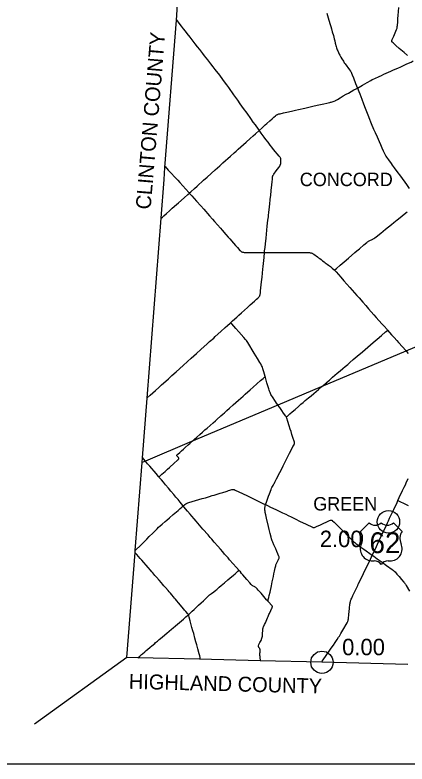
# Model space of a CAD drawing. Extents: x 1597222 to 1925846, y 496284 to 911751.
# Drawn here: x 1652634 to 1678855, y 496867 to 546977 of the extents above; entities that cross this region are included whole.
import ezdxf

# ---------------------------------------------------------------- set-up
doc = ezdxf.new("R2010")
doc.units = 0
for name, color, linetype in [('Default', 7, 'Continuous'), ('GM_X_Adjacent_County', 7, 'Continuous'), ('GM_X_Adjacent_County_Text', 7, 'Continuous'), ('GM_X_County', 7, 'Continuous'), ('GM_X_County_Road', 7, 'Continuous'), ('GM_X_Township', 7, 'Continuous'), ('GM_X_Township_Road', 7, 'Continuous'), ('GM_X_Township_Text', 7, 'Continuous'), ('GM_X_US_Route', 7, 'Continuous'), ('GM_X_US_Shield', 7, 'Continuous'), ('SC_Scratch1', 7, 'Continuous')]:
    doc.layers.add(name, color=color, linetype=linetype)

msp = doc.modelspace()

# ---------------------------------------------------------------- linework, layer by layer
at = {"layer": 'Default'}
for centre in [(1677611, 513068), (1677611, 513068), (1673168, 503670), (1673168, 503670)]:
    msp.add_circle(centre, 750, dxfattribs=at)
at = {"layer": 'GM_X_Adjacent_County'}
msp.add_line((1660124, 503996), (1653936, 499536), dxfattribs=at)
at = {"layer": 'GM_X_County'}
msp.add_lwpolyline([(1678903, 503534), (1673166, 503675), (1669035, 503777), (1664966, 503877), (1660848, 503978), (1660124, 503996), (1660668, 511007), (1660679, 511141), (1661136, 517041), (1661161, 517359), (1661469, 521334), (1662403, 533380), (1662603, 535965), (1662666, 536773), (1663431, 546640), (1663512, 547675)], dxfattribs=at)
at = {"layer": 'GM_X_County_Road'}
for points in [[(1673498, 547096), (1673586, 546780), (1673690, 546418), (1673753, 546197), (1673795, 546055), (1673856, 545851), (1673928, 545598), (1673982, 545392), (1674017, 545249), (1674056, 545089), (1674112, 544867), (1674139, 544772), (1674160, 544709), (1674184, 544648), (1674218, 544573), (1674318, 544366), (1674364, 544279), (1674435, 544150), (1674502, 544037), (1674597, 543883), (1674660, 543787), (1674717, 543707), (1675018, 543297), (1675065, 543229), (1675091, 543188), (1675114, 543145), (1675141, 543086), (1675184, 542979), (1675266, 542765), (1675314, 542643), (1675356, 542536), (1675416, 542383), (1675472, 542246), (1675533, 542090)], [(1675533, 542090), (1675880, 542286), (1676194, 542464), (1676435, 542603), (1676521, 542651), (1676594, 542688), (1676698, 542737), (1676982, 542865), (1677147, 542938), (1677312, 543011), (1677611, 543146), (1677776, 543218), (1677911, 543279), (1678060, 543347), (1678240, 543426), (1678435, 543514), (1678809, 543682), (1679063, 543796), (1679138, 543831), (1679196, 543862), (1679238, 543887), (1679273, 543912)], [(1668974, 539258), (1669157, 539423), (1669376, 539621), (1669486, 539719), (1669682, 539894), (1669828, 540026), (1669950, 540136), (1670061, 540233), (1670112, 540274), (1670152, 540301), (1670180, 540317), (1670210, 540330), (1670240, 540341), (1670287, 540355), (1670367, 540374), (1670591, 540423), (1670927, 540499), (1671215, 540566), (1671391, 540605), (1671599, 540653), (1672031, 540751), (1672559, 540869), (1672847, 540934), (1673295, 541035), (1673487, 541079), (1673583, 541101), (1673695, 541128), (1673743, 541140), (1673760, 541143), (1673776, 541147), (1673839, 541165), (1673917, 541191), (1673979, 541215), (1674039, 541242), (1674083, 541264), (1674197, 541330), (1674382, 541436), (1674595, 541558), (1674795, 541672), (1674938, 541753), (1675109, 541850), (1675308, 541963), (1675451, 542044), (1675533, 542090)], [(1675533, 542090), (1675623, 541865), (1675689, 541697), (1675824, 541345), (1675944, 541040), (1676063, 540734), (1676235, 540290), (1676347, 540000), (1676413, 539832), (1676505, 539603), (1676568, 539452), (1676620, 539331), (1676715, 539122), (1676850, 538823), (1676982, 538523), (1677075, 538313), (1677174, 538088), (1677262, 537893), (1677330, 537744), (1677366, 537670), (1677398, 537612), (1677440, 537542), (1677486, 537473), (1677618, 537286), (1677792, 537047), (1677869, 536940), (1678005, 536756), (1678247, 536425), (1678353, 536278), (1678527, 536040), (1678710, 535787), (1678825, 535628), (1679008, 535376)], [(1664301, 535065), (1664310, 535073), (1664395, 535150), (1664639, 535370), (1664810, 535522), (1665251, 535916), (1665482, 536125), (1665751, 536366), (1666031, 536618), (1666325, 536881), (1666544, 537078), (1667057, 537538), (1667288, 537747), (1667423, 537868), (1667569, 538000), (1667740, 538153), (1668095, 538470), (1668364, 538710), (1668572, 538896), (1668718, 539028), (1668974, 539258)], [(1662674, 536831), (1662885, 536604), (1663052, 536423), (1663353, 536099), (1663520, 535918), (1663654, 535773), (1663864, 535543), (1664263, 535108), (1664301, 535065)], [(1662406, 533379), (1662497, 533459), (1662582, 533536), (1662766, 533699), (1662962, 533874), (1663158, 534048), (1663440, 534299), (1663563, 534407), (1663956, 534755), (1664189, 534963), (1664301, 535065)], [(1664301, 535065), (1664340, 535022), (1664459, 534887), (1664774, 534531), (1665056, 534211), (1665262, 533976), (1665642, 533546), (1665847, 533311), (1665988, 533151), (1666171, 532941), (1666377, 532707), (1666495, 532571), (1666745, 532288), (1666896, 532115), (1667005, 531993), (1667254, 531709), (1667383, 531561), (1667514, 531413), (1667675, 531227), (1667709, 531192), (1667734, 531171), (1667760, 531152), (1667788, 531136), (1667817, 531123), (1667848, 531112), (1667879, 531105), (1667911, 531100), (1667960, 531098), (1668074, 531096), (1668468, 531096), (1668731, 531096), (1669206, 531096), (1669322, 531094)], [(1674007, 529912), (1674052, 529950), (1674139, 530025), (1674388, 530238), (1674662, 530473), (1674948, 530718), (1675372, 531080), (1675509, 531198), (1675671, 531337), (1675971, 531591), (1676170, 531762), (1676222, 531804), (1676262, 531832), (1676290, 531850), (1676333, 531874), (1676378, 531895), (1676515, 531950), (1676559, 531971), (1676602, 531994), (1676643, 532020), (1676697, 532058), (1676787, 532129), (1677106, 532385), (1677424, 532644), (1677807, 532953), (1677973, 533088), (1678202, 533274), (1678406, 533439), (1678534, 533542), (1678662, 533644), (1678866, 533809)], [(1667066, 526400), (1667190, 526511), (1667470, 526763), (1667616, 526895), (1667787, 527048), (1668176, 527400), (1668371, 527577), (1668650, 527830), (1668797, 527961), (1668870, 528027), (1668917, 528073), (1668950, 528110), (1668970, 528135), (1668988, 528163), (1669004, 528191), (1669016, 528222), (1669027, 528253), (1669035, 528285), (1669041, 528317), (1669047, 528366), (1669062, 528512), (1669124, 529116), (1669158, 529442), (1669213, 529981), (1669231, 530160), (1669293, 530764), (1669322, 531094)], [(1669322, 531094), (1669403, 531093), (1669567, 531093), (1669862, 531092), (1670092, 531090), (1670420, 531090), (1670912, 531087), (1671273, 531087), (1671618, 531086), (1671815, 531085), (1671947, 531084), (1672032, 531084), (1672119, 531085), (1672209, 531087), (1672280, 531086), (1672343, 531081), (1672387, 531076), (1672421, 531069), (1672455, 531060), (1672495, 531046), (1672517, 531036), (1672544, 531021), (1672573, 531005), (1672616, 530977), (1672702, 530917), (1672784, 530857), (1672858, 530799), (1672936, 530741), (1673019, 530678), (1673110, 530608), (1673204, 530537), (1673308, 530457), (1673391, 530395), (1673510, 530310), (1673608, 530238), (1673733, 530142), (1673856, 530045), (1673989, 529930), (1674007, 529912)], [(1674007, 529912), (1674123, 529788), (1674262, 529626), (1674429, 529442), (1674638, 529203), (1675031, 528750), (1675497, 528218), (1675648, 528045), (1675896, 527761), (1676091, 527539), (1676286, 527318), (1676632, 526923), (1676795, 526739), (1677178, 526311), (1677320, 526152), (1677517, 525932), (1677556, 525888)], [(1661474, 521356), (1661685, 521545), (1662038, 521864), (1662245, 522051), (1662440, 522226), (1662575, 522347), (1662892, 522631), (1663134, 522852), (1663414, 523106), (1663875, 523525), (1664168, 523788), (1664424, 524018), (1664766, 524325), (1665071, 524599), (1665484, 524973), (1665654, 525128), (1665924, 525367), (1666034, 525466), (1666398, 525797), (1666690, 526060), (1666848, 526203), (1667031, 526368), (1667066, 526400)], [(1677556, 525888), (1677822, 525589), (1677996, 525392), (1678171, 525197), (1678282, 525076), (1678794, 524499)], [(1678794, 524499), (1678816, 524474), (1678936, 524340)], [(1661360, 517134), (1661349, 517147), (1661165, 517366)], [(1662262, 516067), (1662239, 516094), (1662069, 516298), (1661935, 516455), (1661783, 516633), (1661648, 516791), (1661506, 516958), (1661360, 517134)], [(1663887, 514129), (1663864, 514158), (1663677, 514385), (1663540, 514552), (1663393, 514729), (1663248, 514906), (1663067, 515120), (1662891, 515329), (1662708, 515545), (1662561, 515715), (1662430, 515870), (1662262, 516067)], [(1663887, 514129), (1664005, 514225), (1664057, 514265), (1664084, 514283), (1664112, 514300), (1664142, 514314), (1664187, 514333), (1664265, 514359), (1664705, 514489), (1665146, 514620), (1665366, 514685), (1665648, 514770), (1665821, 514821), (1665963, 514862), (1666167, 514923), (1666355, 514981), (1666528, 515033), (1666762, 515108), (1666825, 515127), (1666919, 515156), (1667013, 515187), (1667137, 515228), (1667169, 515236), (1667185, 515239), (1667201, 515241), (1667218, 515242), (1667234, 515241), (1667250, 515239), (1667266, 515236), (1667297, 515225), (1667357, 515198), (1667609, 515079), (1667860, 514958), (1668185, 514802), (1668451, 514674), (1668629, 514589), (1669087, 514368), (1669263, 514281), (1669382, 514225), (1669394, 514220)], [(1669394, 514220), (1669530, 514154), (1669722, 514061), (1670076, 513891), (1670520, 513678), (1670742, 513572), (1670904, 513493), (1671097, 513402), (1671377, 513265), (1671716, 513100), (1672056, 512937), (1672233, 512851), (1672395, 512771), (1672483, 512728), (1672528, 512708), (1672559, 512698), (1672575, 512695), (1672592, 512693), (1672608, 512692), (1672624, 512693), (1672641, 512694), (1672657, 512697), (1672673, 512701), (1672704, 512712), (1672794, 512751), (1673063, 512873), (1673197, 512934), (1673541, 513088), (1673676, 513149), (1673735, 513176), (1673751, 513182), (1673767, 513186), (1673783, 513189), (1673799, 513189), (1673815, 513186), (1673831, 513180), (1673845, 513172), (1673858, 513163), (1673882, 513140), (1673975, 513048), (1674184, 512839), (1674359, 512667), (1674488, 512540), (1674686, 512345), (1674813, 512216), (1674917, 512111), (1675058, 511975), (1675151, 511882), (1675232, 511800), (1675304, 511733), (1675354, 511691), (1675431, 511630), (1675564, 511534), (1675777, 511381), (1675977, 511238), (1676532, 510836)], [(1667608, 509824), (1667554, 509891), (1667529, 509919), (1667423, 510039), (1667228, 510261), (1666990, 510534), (1666885, 510658), (1666776, 510782), (1666657, 510916), (1666526, 511068), (1666377, 511237), (1666193, 511449), (1665958, 511719), (1665795, 511909), (1665691, 512030), (1665549, 512193), (1665204, 512589), (1664742, 513121), (1664615, 513268), (1664464, 513442), (1664347, 513579), (1664176, 513779), (1663925, 514082), (1663887, 514129)], [(1676532, 510836), (1676630, 510767), (1676856, 510604), (1677189, 510365), (1677482, 510154), (1677855, 509886), (1677920, 509837), (1677971, 509795), (1678007, 509762), (1678052, 509714), (1678172, 509579), (1678324, 509408), (1678496, 509210), (1678648, 509037), (1678690, 508987), (1678719, 508947), (1678755, 508893), (1678806, 508808), (1679028, 508425)], [(1664245, 506854), (1664279, 506887), (1664351, 506958), (1664493, 507093), (1664612, 507206), (1664911, 507486), (1665091, 507654), (1665235, 507788), (1665355, 507900), (1665474, 508013), (1665558, 508092), (1665653, 508181), (1665703, 508224), (1665767, 508274), (1665926, 508390), (1666058, 508488), (1666135, 508550), (1666298, 508688), (1666435, 508805), (1666646, 508987), (1666868, 509182), (1667004, 509300), (1667240, 509504), (1667352, 509600), (1667452, 509685), (1667464, 509696), (1667514, 509739), (1667551, 509772), (1667608, 509824)], [(1665028, 503879), (1665026, 503934), (1665024, 503951), (1665015, 503999), (1664991, 504095), (1664954, 504238), (1664865, 504571), (1664792, 504840), (1664735, 505045), (1664671, 505283), (1664587, 505600), (1664539, 505774), (1664473, 506011), (1664426, 506185), (1664357, 506438), (1664288, 506691), (1664263, 506787), (1664251, 506829), (1664245, 506854)]]:
    msp.add_lwpolyline(points, dxfattribs=at)
at = {"layer": 'GM_X_Township'}
msp.add_lwpolyline([(1697617, 533364), (1689097, 533498), (1689075, 533471), (1686122, 529882), (1685324, 528919), (1683211, 526366), (1678773, 524491), (1673121, 522104), (1670207, 520873), (1664451, 518441), (1661353, 517132), (1661136, 517041)], dxfattribs=at)
at = {"layer": 'GM_X_Township_Road'}
for points in [[(1678879, 544266), (1678657, 544461), (1678338, 544744), (1678117, 544940), (1678019, 545027), (1677970, 545071), (1677933, 545103), (1677871, 545156), (1677848, 545179), (1677840, 545192), (1677835, 545206), (1677834, 545222), (1677836, 545237), (1677840, 545252), (1677846, 545267), (1677872, 545327), (1677910, 545418), (1677967, 545554), (1678059, 545782), (1678152, 546010), (1678170, 546056), (1678186, 546103), (1678199, 546151), (1678207, 546199), (1678215, 546265), (1678235, 546527), (1678252, 546739), (1678267, 546935), (1678310, 547475)], [(1668974, 539258), (1668919, 539335), (1668710, 539629), (1668576, 539816), (1668414, 540043), (1668157, 540403), (1667927, 540723), (1667699, 541044), (1667538, 541272), (1667280, 541632), (1666927, 542126), (1666794, 542314), (1666652, 542514), (1666545, 542660), (1666326, 542947), (1666024, 543335), (1665882, 543516), (1665732, 543711), (1665530, 543970), (1665319, 544242), (1665198, 544397), (1664997, 544657), (1664844, 544850), (1664694, 545045), (1664353, 545486), (1664151, 545745), (1664041, 545888), (1663910, 546057), (1663778, 546224), (1663689, 546342), (1663568, 546497), (1663437, 546666)], [(1669322, 531094), (1669333, 531207), (1669357, 531419), (1669383, 531663), (1669425, 532038), (1669512, 532854), (1669555, 533246), (1669580, 533474), (1669591, 533572), (1669615, 533784), (1669651, 534110), (1669678, 534371), (1669702, 534583), (1669712, 534665), (1669738, 534909), (1669773, 535236), (1669815, 535611), (1669835, 535807), (1669850, 535986), (1669861, 536117), (1669868, 536166), (1669875, 536198), (1669886, 536229), (1669899, 536259), (1669916, 536287), (1669943, 536328), (1670097, 536541), (1670272, 536779), (1670339, 536872), (1670366, 536913), (1670382, 536942), (1670394, 536972), (1670403, 537004), (1670406, 537020), (1670409, 537052), (1670413, 537134), (1670419, 537249), (1670421, 537298), (1670419, 537331), (1670414, 537363), (1670409, 537379), (1670397, 537409), (1670390, 537424), (1670373, 537452), (1670353, 537478), (1670301, 537542), (1669933, 537983), (1669809, 538136), (1669707, 538265), (1669558, 538460), (1669421, 538645), (1669305, 538804), (1669100, 539080), (1669004, 539213), (1668974, 539258)], [(1669368, 522791), (1669324, 522937), (1669276, 523094), (1669211, 523315), (1669182, 523408), (1669159, 523470), (1669133, 523530), (1669104, 523589), (1669072, 523646), (1669021, 523730), (1668857, 523995), (1668635, 524359), (1668506, 524569), (1668344, 524835), (1668198, 525073), (1668153, 525142), (1668114, 525194), (1668063, 525258), (1667933, 525406), (1667598, 525789), (1667413, 525998), (1667132, 526318), (1667090, 526369), (1667080, 526382), (1667066, 526400)], [(1673459, 522374), (1673472, 522385), (1673671, 522556), (1673882, 522739), (1674192, 523007), (1674390, 523179), (1674566, 523327), (1674728, 523466), (1674891, 523604), (1675041, 523732), (1675264, 523925), (1675526, 524149), (1675875, 524448), (1676050, 524597), (1676237, 524757), (1676599, 525066), (1676861, 525290), (1677146, 525537), (1677422, 525771), (1677521, 525857), (1677556, 525888)], [(1664568, 518529), (1664643, 518595), (1664790, 518724), (1664999, 518910), (1665171, 519062), (1665343, 519213), (1665491, 519344), (1665687, 519518), (1665882, 519694), (1666043, 519834), (1666129, 519910), (1666412, 520160), (1666546, 520280), (1666644, 520367), (1666804, 520508), (1666987, 520672), (1667233, 520890), (1667415, 521055), (1667587, 521208), (1667894, 521480), (1668040, 521611), (1668371, 521906), (1668555, 522070), (1669059, 522514), (1669230, 522668), (1669328, 522755), (1669368, 522791)], [(1670144, 520991), (1670136, 521002), (1670053, 521124), (1669856, 521427), (1669796, 521524), (1669756, 521596), (1669727, 521655), (1669693, 521730), (1669662, 521806), (1669640, 521867), (1669611, 521961), (1669490, 522370), (1669386, 522733), (1669368, 522791)], [(1673162, 522120), (1673172, 522129), (1673260, 522204), (1673459, 522374)], [(1670785, 520087), (1670809, 520104), (1670822, 520114), (1670860, 520145), (1671019, 520287), (1671181, 520426), (1671367, 520588), (1671589, 520782), (1671763, 520932), (1671914, 521059), (1672051, 521177), (1672164, 521272), (1672276, 521368), (1672440, 521505), (1672616, 521652), (1672941, 521929), (1673162, 522120)], [(1670223, 520879), (1670144, 520991)], [(1670785, 520087), (1670774, 520107), (1670747, 520149), (1670603, 520348), (1670489, 520508), (1670345, 520708), (1670223, 520879)], [(1669394, 514220), (1669394, 514223), (1669409, 514270), (1669449, 514377), (1669476, 514453), (1669521, 514576), (1669595, 514777), (1669657, 514946), (1669763, 515239), (1669793, 515316), (1669820, 515375), (1669850, 515434), (1669892, 515504), (1669951, 515602), (1669983, 515660), (1670021, 515732), (1670126, 515937), (1670342, 516360), (1670499, 516667), (1670573, 516814), (1670684, 517033), (1670825, 517311), (1671002, 517663), (1671084, 517824), (1671227, 518100), (1671297, 518231), (1671310, 518261), (1671321, 518292), (1671324, 518308), (1671327, 518324), (1671328, 518340), (1671327, 518357), (1671325, 518373), (1671319, 518405), (1671299, 518468), (1671238, 518655), (1671160, 518905), (1671096, 519109), (1671048, 519266), (1670981, 519485), (1670889, 519783), (1670819, 520002), (1670803, 520048), (1670790, 520078), (1670785, 520087)], [(1662262, 516067), (1662279, 516082), (1662304, 516104), (1662460, 516248), (1662678, 516447), (1662835, 516591), (1662969, 516712), (1663286, 516996), (1663480, 517171), (1663555, 517236), (1663567, 517247), (1663578, 517259), (1663587, 517273), (1663592, 517287), (1663595, 517303), (1663593, 517319), (1663588, 517334), (1663581, 517349), (1663571, 517363), (1663561, 517375), (1663495, 517449), (1663485, 517462), (1663476, 517476), (1663469, 517490), (1663465, 517506), (1663465, 517521), (1663470, 517537), (1663477, 517551), (1663487, 517564), (1663498, 517576), (1663523, 517599), (1663658, 517718), (1663781, 517826), (1663903, 517934), (1664026, 518043), (1664221, 518218), (1664331, 518316), (1664428, 518404), (1664486, 518455)], [(1664486, 518455), (1664556, 518519), (1664568, 518529)], [(1669552, 507763), (1669558, 507785), (1669563, 507804), (1669570, 507836), (1669579, 507869), (1669611, 508002), (1669642, 508147), (1669692, 508371), (1669783, 508788), (1669842, 509060), (1669919, 509413), (1669958, 509589), (1669997, 509765), (1670045, 509995), (1670075, 510136), (1670087, 510185), (1670101, 510228), (1670130, 510289), (1670165, 510363), (1670252, 510540), (1670288, 510613), (1670300, 510644), (1670304, 510660), (1670306, 510676), (1670307, 510692), (1670305, 510708), (1670302, 510724), (1670292, 510756), (1670221, 510922), (1670149, 511087), (1670071, 511268), (1670031, 511358), (1669957, 511523), (1669871, 511718), (1669840, 511794), (1669818, 511856), (1669795, 511934), (1669767, 512046), (1669708, 512284), (1669641, 512555), (1669591, 512762), (1669456, 513321), (1669408, 513528), (1669376, 513689), (1669358, 513786), (1669350, 513851), (1669345, 513900), (1669344, 513949), (1669346, 513982), (1669352, 514031), (1669360, 514080), (1669374, 514144), (1669394, 514220)], [(1678250, 514495), (1678279, 514481), (1678368, 514438), (1678663, 514294), (1678943, 514157)], [(1660683, 511153), (1661072, 511531), (1661270, 511728), (1661455, 511914), (1661617, 512077), (1661848, 512309), (1661941, 512402), (1662137, 512600), (1662243, 512702), (1662340, 512791), (1662475, 512910), (1662674, 513081), (1662798, 513188), (1662959, 513328), (1663219, 513553), (1663442, 513746), (1663541, 513832), (1663677, 513951), (1663788, 514048), (1663838, 514090), (1663864, 514110), (1663887, 514129)], [(1664245, 506854), (1664222, 506886), (1664196, 506916), (1664065, 507064), (1663979, 507163), (1663917, 507237), (1663803, 507379), (1663709, 507491), (1663570, 507654), (1663451, 507789), (1663367, 507889), (1663314, 507953), (1663240, 508041), (1663115, 508191), (1663032, 508290), (1662945, 508390), (1662880, 508466), (1662697, 508674), (1662589, 508798), (1662502, 508898), (1662428, 508983), (1662277, 509159), (1662107, 509357), (1661999, 509478), (1661847, 509654), (1661783, 509728), (1661697, 509826), (1661535, 510012), (1661404, 510161), (1661246, 510348), (1661113, 510496), (1661016, 510608), (1660781, 510877), (1660671, 511005)], [(1669552, 507763), (1669512, 507808), (1669466, 507860), (1669092, 508294), (1668908, 508503), (1668832, 508589), (1668786, 508636), (1668762, 508658), (1668736, 508678), (1668708, 508695), (1668679, 508711), (1668635, 508732), (1668560, 508767), (1668532, 508783), (1668505, 508802), (1668493, 508813), (1668469, 508835), (1668425, 508884), (1668340, 508984), (1668137, 509220), (1668008, 509368), (1667878, 509517), (1667792, 509616), (1667707, 509715), (1667608, 509824)], [(1669064, 503782), (1669057, 503833), (1669040, 503947), (1669030, 504012), (1669024, 504061), (1669018, 504126), (1669016, 504192), (1669016, 504241), (1669019, 504290), (1669025, 504339), (1669029, 504371), (1669032, 504420), (1669032, 504469), (1669031, 504502), (1669029, 504518), (1669026, 504534), (1669022, 504550), (1669016, 504566), (1669009, 504580), (1669001, 504595), (1668982, 504621), (1668952, 504661), (1668935, 504688), (1668927, 504703), (1668921, 504718), (1668916, 504733), (1668912, 504749), (1668910, 504766), (1668910, 504782), (1668912, 504798), (1668916, 504814), (1668922, 504829), (1668937, 504858), (1668971, 504915), (1669013, 504986), (1669053, 505057), (1669092, 505129), (1669112, 505174), (1669131, 505219), (1669151, 505282), (1669173, 505361), (1669183, 505409), (1669191, 505457), (1669196, 505506), (1669199, 505621), (1669203, 505768), (1669208, 505850), (1669213, 505899), (1669218, 505931), (1669227, 505963), (1669238, 505994), (1669265, 506053), (1669334, 506202), (1669380, 506307), (1669433, 506427), (1669479, 506532), (1669524, 506638), (1669563, 506728), (1669623, 506863), (1669656, 506937), (1669751, 507147), (1669820, 507296), (1669834, 507326), (1669840, 507341), (1669845, 507357), (1669848, 507373), (1669849, 507389), (1669847, 507405), (1669843, 507421), (1669837, 507436), (1669829, 507450), (1669819, 507463), (1669788, 507501), (1669623, 507684), (1669590, 507721), (1669575, 507738), (1669552, 507763)], [(1660860, 503979), (1660981, 504085), (1661105, 504192), (1661167, 504246), (1661316, 504374), (1661416, 504459), (1661504, 504533), (1661679, 504682), (1661791, 504778), (1661978, 504937), (1662041, 504990), (1662091, 505032), (1662166, 505096), (1662279, 505191), (1662481, 505359), (1662657, 505506), (1662782, 505613), (1662945, 505749), (1663107, 505889), (1663220, 505983), (1663371, 506109), (1663497, 506215), (1663634, 506332), (1663772, 506448), (1663909, 506566), (1664069, 506706), (1664182, 506800), (1664220, 506832), (1664245, 506854)]]:
    msp.add_lwpolyline(points, dxfattribs=at)
at = {"layer": 'GM_X_US_Route'}
msp.add_lwpolyline([(1673147, 503684), (1673184, 503749), (1673238, 503831), (1673443, 504128), (1673640, 504411), (1673789, 504627), (1673930, 504829), (1674042, 504990), (1674191, 505206), (1674282, 505343), (1674334, 505427), (1674434, 505596), (1674632, 505937), (1674788, 506206), (1674845, 506307), (1674875, 506365), (1674888, 506396), (1674899, 506427), (1674912, 506475), (1674922, 506523), (1674931, 506588), (1674966, 506898), (1674982, 507045), (1675008, 507290), (1675035, 507551), (1675045, 507632), (1675053, 507680), (1675067, 507744), (1675081, 507791), (1675097, 507837), (1675121, 507898), (1675155, 507973), (1675241, 508149), (1675385, 508444), (1675557, 508799), (1675599, 508888), (1675719, 509139), (1675946, 509613), (1676237, 510219), (1676337, 510426), (1676479, 510722), (1676532, 510836), (1676625, 511034), (1676716, 511227), (1676807, 511419), (1676955, 511731), (1677115, 512073), (1677212, 512281), (1677268, 512399), (1677408, 512696), (1677553, 513009), (1677615, 513142), (1677692, 513306), (1677825, 513588), (1677964, 513885), (1678187, 514360), (1678250, 514495), (1678341, 514687), (1678564, 515162), (1678667, 515385), (1678744, 515549), (1678807, 515682), (1678940, 515964)], dxfattribs=at)
at = {"layer": 'GM_X_US_Shield'}
for p, q in [((1676320, 513006), (1675740, 512426)), ((1678524, 512426), (1677944, 513006)), ((1676552, 510454), (1676668, 510454)), ((1677596, 510454), (1677712, 510454))]:
    msp.add_line(p, q, dxfattribs=at)
for centre, radius, start, end in [((1676726, 513420), 580, 225.573, 314.427), ((1677538, 513420), 580, 225.573, 314.427), ((1675075, 511960), 812, 334.5471, 35.0009), ((1679190, 511960), 812, 144.9991, 205.4529), ((1676543, 511266), 812, 154.8319, 270.6383), ((1677721, 511266), 812, 269.3617, 25.1681), ((1676668, 509873), 580, 36.8699, 90), ((1677596, 509873), 580, 90, 143.1301)]:
    msp.add_arc(centre, radius, start, end, dxfattribs=at)
at = {"layer": 'SC_Scratch1'}
msp.add_lwpolyline([(1597222, 631367), (1793472, 631367), (1793472, 496867), (1597222, 496867)], close=True, dxfattribs=at)

# ---------------------------------------------------------------- texts
at = {"layer": 'Default'}
for s, p in [('2.00', (1673020, 511378)), ('2.00', (1673020, 511378)), ('0.00', (1674516, 504144)), ('0.00', (1674516, 504144))]:
    msp.add_text(s, height=1100, dxfattribs=at).set_placement(p)
at = {"layer": 'GM_X_Adjacent_County_Text'}
for s, rotation, p in [('CLINTON COUNTY', 85.2248, (1661702, 533937)), ('HIGHLAND COUNTY', 358.5749, (1660238, 501901))]:
    msp.add_text(s, height=1000, rotation=rotation, dxfattribs=at).set_placement(p)
at = {"layer": 'GM_X_Township_Text'}
for s, p in [('CONCORD', (1671685, 535527)), ('GREEN', (1672583, 513826))]:
    msp.add_text(s, height=900, rotation=0, dxfattribs=at).set_placement(p)
at = {"layer": 'GM_X_US_Shield'}
msp.add_text('62', height=1392.2, dxfattribs=at).set_placement((1676344, 510976))

doc.saveas('drawing.dxf')
